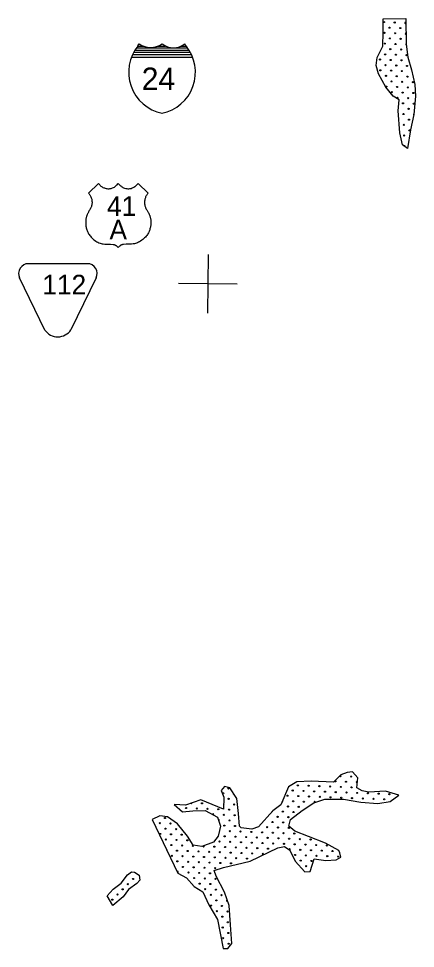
# Model space of a CAD drawing. Extents: x 1612280 to 1883141, y 560852 to 780851.
# Drawn here: x 1694945 to 1702393, y 716820 to 734263 of the extents above; entities that cross this region are included whole.
import ezdxf

# ---------------------------------------------------------------- set-up
doc = ezdxf.new("R2010")
doc.units = 0
for name, color, linetype in [('DESIGN - ROW - Easement Linework and Patterning', 7, 'Continuous'), ('DESIGN - SCRATCH - User 1', 7, 'Continuous'), ('DESIGN - TRAFFIC CONTROL PERMANENT - Pavement Marking Text', 7, 'Continuous'), ('SURVEY - DRAINAGE - Bridge Deck with Text', 7, 'Continuous'), ('SURVEY - DRAINAGE - Bridge Hydraulic Data - Points - Locators', 7, 'Continuous'), ('SURVEY - DRAINAGE - Bridge Hydraulic Data with Text', 7, 'Continuous')]:
    doc.layers.add(name, color=color, linetype=linetype)

msp = doc.modelspace()

# ---------------------------------------------------------------- linework, layer by layer
at = {"layer": 'DESIGN - ROW - Easement Linework and Patterning'}
for p, q in [((1696234, 729665), (1695130, 729665)), ((1696234, 729665), (1695130, 729665)), ((1695438, 728419), (1694963, 729399)), ((1695438, 728419), (1694963, 729399)), ((1696400, 729400), (1695927, 728422)), ((1696400, 729400), (1695927, 728422))]:
    msp.add_line(p, q, dxfattribs=at)
for centre, radius, start, end in [((1695130, 729480), 185, 90.0012, 205.8236), ((1695130, 729480), 185, 90.0012, 205.8236), ((1696234, 729480), 185, 334.1799, 90.0012), ((1696234, 729480), 185, 334.1799, 90.0012), ((1695681, 728591), 298, 215.137, 325.5451), ((1695681, 728591), 298, 215.137, 325.5451)]:
    msp.add_arc(centre, radius, start, end, dxfattribs=at)
at = {"layer": 'DESIGN - SCRATCH - User 1'}
for points in [[(1702243, 731826), (1702148, 731893), (1702103, 732117), (1702069, 732530), (1702086, 732737), (1701974, 732810), (1701840, 732977), (1701701, 733229), (1701656, 733385), (1701678, 733531), (1701779, 733743), (1701790, 734006), (1701790, 734257)], [(1702243, 731826), (1702148, 731893), (1702103, 732117), (1702069, 732530), (1702086, 732737), (1701974, 732810), (1701840, 732977), (1701701, 733229), (1701656, 733385), (1701678, 733531), (1701779, 733743), (1701790, 734006), (1701790, 734257)], [(1701790, 734257), (1702215, 734263)], [(1701790, 734257), (1702215, 734263)], [(1702215, 734263), (1702220, 733782), (1702254, 733542), (1702321, 733302), (1702382, 733028), (1702393, 732810), (1702365, 732463), (1702304, 732178), (1702243, 731826)], [(1702215, 734263), (1702220, 733782), (1702254, 733542), (1702321, 733302), (1702382, 733028), (1702393, 732810), (1702365, 732463), (1702304, 732178), (1702243, 731826)], [(1702085, 719696), (1701830, 719771), (1701520, 719751), (1701395, 719776), (1701295, 719831), (1701315, 720021), (1701210, 720131), (1701111, 720121), (1700996, 720076), (1700856, 719936), (1700436, 719956), (1700169, 719944)], [(1702085, 719696), (1701830, 719771), (1701520, 719751), (1701395, 719776), (1701295, 719831), (1701315, 720021), (1701210, 720131), (1701111, 720121), (1700996, 720076), (1700856, 719936), (1700436, 719956), (1700169, 719944)], [(1700169, 719944), (1700009, 719849), (1699869, 719514), (1699719, 719399), (1699450, 719099), (1699320, 719054), (1699120, 719079), (1699090, 719114), (1699070, 719349), (1699040, 719634), (1698910, 719829), (1698810, 719854), (1698745, 719779), (1698800, 719654), (1698790, 719429), (1698366, 719604), (1698076, 719509), (1697866, 719519)], [(1700169, 719944), (1700009, 719849), (1699869, 719514), (1699719, 719399), (1699450, 719099), (1699320, 719054), (1699120, 719079), (1699090, 719114), (1699070, 719349), (1699040, 719634), (1698910, 719829), (1698810, 719854), (1698745, 719779), (1698800, 719654), (1698790, 719429), (1698366, 719604), (1698076, 719509), (1697866, 719519)], [(1700494, 718499), (1700711, 718467), (1700906, 718482), (1700996, 718532), (1700976, 718612), (1700956, 718657), (1700706, 718792), (1700386, 718916), (1700127, 719021), (1700017, 719116), (1700047, 719236), (1700266, 719406), (1700486, 719551), (1700691, 719621), (1701041, 719621), (1701370, 719566), (1701690, 719541), (1701920, 719576), (1702085, 719696)], [(1700494, 718499), (1700711, 718467), (1700906, 718482), (1700996, 718532), (1700976, 718612), (1700956, 718657), (1700706, 718792), (1700386, 718916), (1700127, 719021), (1700017, 719116), (1700047, 719236), (1700266, 719406), (1700486, 719551), (1700691, 719621), (1701041, 719621), (1701370, 719566), (1701690, 719541), (1701920, 719576), (1702085, 719696)], [(1697866, 719519), (1698021, 719384), (1698216, 719399), (1698446, 719404), (1698676, 719284), (1698735, 719114), (1698691, 718924), (1698606, 718814), (1698386, 718734), (1698221, 718754), (1698116, 718924), (1697926, 719154), (1697737, 719289), (1697597, 719304), (1697452, 719239)], [(1697866, 719519), (1698021, 719384), (1698216, 719399), (1698446, 719404), (1698676, 719284), (1698735, 719114), (1698691, 718924), (1698606, 718814), (1698386, 718734), (1698221, 718754), (1698116, 718924), (1697926, 719154), (1697737, 719289), (1697597, 719304), (1697452, 719239)], [(1697452, 719239), (1697931, 718234)], [(1697452, 719239), (1697931, 718234)], [(1698616, 718279), (1698790, 718339), (1699290, 718454), (1699809, 718704), (1699939, 718729), (1700039, 718664), (1700139, 718459), (1700319, 718254), (1700419, 718264), (1700494, 718499)], [(1698616, 718279), (1698790, 718339), (1699290, 718454), (1699809, 718704), (1699939, 718729), (1700039, 718664), (1700139, 718459), (1700319, 718254), (1700419, 718264), (1700494, 718499)], [(1696605, 717803), (1696717, 717929), (1696871, 718043), (1696989, 718202), (1697067, 718258), (1697123, 718251), (1697205, 718191)], [(1696605, 717803), (1696717, 717929), (1696871, 718043), (1696989, 718202), (1697067, 718258), (1697123, 718251), (1697205, 718191)], [(1697205, 718191), (1697221, 718100), (1697163, 718040), (1697009, 717926), (1696905, 717786), (1696711, 717623)], [(1697205, 718191), (1697221, 718100), (1697163, 718040), (1697009, 717926), (1696905, 717786), (1696711, 717623)], [(1697931, 718234), (1698096, 718144), (1698241, 717984), (1698401, 717879), (1698516, 717639), (1698676, 717360), (1698785, 716820), (1698875, 716820), (1698945, 716910), (1698920, 717260), (1698895, 717624), (1698810, 717874), (1698656, 718174), (1698616, 718279)], [(1697931, 718234), (1698096, 718144), (1698241, 717984), (1698401, 717879), (1698516, 717639), (1698676, 717360), (1698785, 716820), (1698875, 716820), (1698945, 716910), (1698920, 717260), (1698895, 717624), (1698810, 717874), (1698656, 718174), (1698616, 718279)], [(1696711, 717623), (1696605, 717803)], [(1696711, 717623), (1696605, 717803)]]:
    msp.add_lwpolyline(points, dxfattribs=at)
for centre in [(1701952, 732883), (1701952, 732883), (1702057, 732778), (1702057, 732778), (1702161, 732674), (1702161, 732674), (1697820, 718557), (1697820, 718557), (1697925, 718452), (1697925, 718452)]:
    msp.add_circle(centre, 10.6, dxfattribs=at)
msp.add_arc((1697716, 718661), 10.6, 20.4261, 30.6046, dxfattribs=at)
at = {"layer": 'DESIGN - TRAFFIC CONTROL PERMANENT - Pavement Marking Text'}
for centre in [(1701803, 734197), (1701803, 734197), (1702004, 734189), (1702004, 734189), (1701810, 733995), (1701810, 733995), (1701907, 734092), (1701907, 734092), (1702109, 734085), (1702109, 734085), (1701915, 733891), (1701915, 733891), (1702012, 733988), (1702012, 733988), (1702116, 733883), (1702116, 733883), (1701818, 733794), (1701818, 733794), (1701922, 733689), (1701922, 733689), (1702019, 733786), (1702019, 733786), (1702124, 733682), (1702124, 733682), (1701728, 733495), (1701728, 733495), (1701825, 733592), (1701825, 733592), (1701930, 733487), (1701930, 733487), (1702027, 733585), (1702027, 733585), (1702131, 733480), (1702131, 733480), (1702229, 733577), (1702229, 733577), (1701736, 733293), (1701736, 733293), (1701833, 733390), (1701833, 733390), (1702034, 733383), (1702034, 733383), (1702236, 733375), (1702236, 733375), (1701840, 733189), (1701840, 733189), (1701937, 733286), (1701937, 733286), (1702042, 733181), (1702042, 733181), (1702139, 733278), (1702139, 733278), (1702243, 733174), (1702243, 733174), (1701848, 732987), (1701848, 732987), (1701945, 733084), (1701945, 733084), (1702049, 732980), (1702049, 732980), (1702146, 733077), (1702146, 733077), (1702251, 732972), (1702251, 732972), (1702348, 733069), (1702348, 733069), (1702154, 732875), (1702154, 732875), (1702258, 732771), (1702258, 732771), (1702355, 732868), (1702355, 732868), (1702363, 732666), (1702363, 732666), (1702169, 732472), (1702169, 732472), (1702266, 732569), (1702266, 732569), (1702176, 732270), (1702176, 732270), (1702273, 732367), (1702273, 732367), (1702281, 732166), (1702281, 732166), (1702184, 732069), (1702184, 732069), (1700986, 720050), (1700986, 720050), (1701188, 720043), (1701188, 720043), (1700187, 719878), (1700187, 719878), (1700389, 719871), (1700389, 719871), (1700591, 719864), (1700591, 719864), (1700889, 719953), (1700889, 719953), (1701091, 719946), (1701091, 719946), (1701293, 719938), (1701293, 719938), (1698784, 719729), (1698784, 719729), (1700090, 719781), (1700090, 719781), (1700292, 719774), (1700292, 719774), (1700494, 719766), (1700494, 719766), (1700695, 719759), (1700695, 719759), (1700792, 719856), (1700792, 719856), (1700897, 719751), (1700897, 719751), (1700994, 719849), (1700994, 719849), (1701098, 719744), (1701098, 719744), (1701195, 719841), (1701195, 719841), (1701300, 719737), (1701300, 719737), (1701502, 719729), (1701502, 719729), (1701703, 719722), (1701703, 719722), (1701905, 719714), (1701905, 719714), (1698388, 719542), (1698388, 719542), (1698888, 719625), (1698888, 719625), (1698993, 719520), (1698993, 719520), (1699993, 719684), (1699993, 719684), (1700098, 719580), (1700098, 719580), (1700195, 719677), (1700195, 719677), (1700299, 719572), (1700299, 719572), (1700396, 719669), (1700396, 719669), (1700598, 719662), (1700598, 719662), (1700800, 719654), (1700800, 719654), (1701001, 719647), (1701001, 719647), (1701203, 719639), (1701203, 719639), (1701405, 719632), (1701405, 719632), (1701606, 719625), (1701606, 719625), (1701808, 719617), (1701808, 719617), (1698089, 719453), (1698089, 719453), (1698291, 719445), (1698291, 719445), (1698492, 719438), (1698492, 719438), (1698694, 719430), (1698694, 719430), (1698896, 719423), (1698896, 719423), (1699904, 719386), (1699904, 719386), (1700001, 719483), (1700001, 719483), (1700105, 719378), (1700105, 719378), (1700202, 719475), (1700202, 719475), (1697596, 719169), (1697596, 719169), (1697693, 719266), (1697693, 719266), (1698799, 719326), (1698799, 719326), (1698903, 719221), (1698903, 719221), (1699000, 719318), (1699000, 719318), (1699710, 719191), (1699710, 719191), (1699807, 719289), (1699807, 719289), (1699911, 719184), (1699911, 719184), (1700008, 719281), (1700008, 719281), (1697701, 719065), (1697701, 719065), (1697798, 719162), (1697798, 719162), (1697902, 719057), (1697902, 719057), (1698806, 719124), (1698806, 719124), (1698911, 719020), (1698911, 719020), (1699008, 719117), (1699008, 719117), (1699112, 719012), (1699112, 719012), (1699314, 719005), (1699314, 719005), (1699515, 718997), (1699515, 718997), (1699612, 719094), (1699612, 719094), (1699717, 718990), (1699717, 718990), (1699814, 719087), (1699814, 719087), (1700016, 719079), (1700016, 719079), (1697604, 718967), (1697604, 718967), (1697708, 718863), (1697708, 718863), (1697805, 718960), (1697805, 718960), (1697910, 718855), (1697910, 718855), (1698007, 718953), (1698007, 718953), (1698112, 718848), (1698112, 718848), (1698716, 718826), (1698716, 718826), (1698813, 718923), (1698813, 718923), (1698918, 718818), (1698918, 718818), (1699015, 718915), (1699015, 718915), (1699217, 718908), (1699217, 718908), (1699418, 718900), (1699418, 718900), (1699620, 718893), (1699620, 718893), (1699822, 718885), (1699822, 718885), (1699919, 718982), (1699919, 718982), (1700023, 718878), (1700023, 718878), (1700120, 718975), (1700120, 718975), (1700225, 718870), (1700225, 718870), (1700426, 718863), (1700426, 718863), (1697813, 718758), (1697813, 718758), (1697917, 718654), (1697917, 718654), (1698014, 718751), (1698014, 718751), (1698119, 718646), (1698119, 718646), (1698216, 718743), (1698216, 718743), (1698619, 718729), (1698619, 718729), (1698821, 718721), (1698821, 718721), (1699023, 718714), (1699023, 718714), (1699120, 718811), (1699120, 718811), (1699224, 718706), (1699224, 718706), (1699321, 718803), (1699321, 718803), (1699426, 718699), (1699426, 718699), (1699523, 718796), (1699523, 718796), (1699627, 718691), (1699627, 718691), (1699724, 718788), (1699724, 718788), (1699926, 718781), (1699926, 718781), (1700128, 718773), (1700128, 718773), (1700232, 718669), (1700232, 718669), (1700329, 718766), (1700329, 718766), (1700434, 718661), (1700434, 718661), (1700531, 718758), (1700531, 718758), (1700635, 718654), (1700635, 718654), (1700732, 718751), (1700732, 718751), (1700837, 718646), (1700837, 718646), (1698022, 718549), (1698022, 718549), (1698224, 718542), (1698224, 718542), (1698321, 718639), (1698321, 718639), (1698425, 718534), (1698425, 718534), (1698522, 718631), (1698522, 718631), (1698627, 718527), (1698627, 718527), (1698724, 718624), (1698724, 718624), (1698828, 718519), (1698828, 718519), (1698925, 718617), (1698925, 718617), (1699030, 718512), (1699030, 718512), (1699127, 718609), (1699127, 718609), (1699232, 718505), (1699232, 718505), (1699329, 718602), (1699329, 718602), (1699530, 718594), (1699530, 718594), (1700135, 718572), (1700135, 718572), (1700240, 718467), (1700240, 718467), (1700337, 718564), (1700337, 718564), (1700538, 718557), (1700538, 718557), (1700740, 718549), (1700740, 718549), (1700942, 718542), (1700942, 718542), (1698029, 718348), (1698029, 718348), (1698126, 718445), (1698126, 718445), (1698231, 718340), (1698231, 718340), (1698328, 718437), (1698328, 718437), (1698433, 718333), (1698433, 718333), (1698530, 718430), (1698530, 718430), (1698634, 718325), (1698634, 718325), (1698731, 718422), (1698731, 718422), (1698933, 718415), (1698933, 718415), (1700344, 718363), (1700344, 718363), (1700441, 718460), (1700441, 718460), (1697094, 718122), (1697094, 718122), (1698134, 718243), (1698134, 718243), (1698239, 718139), (1698239, 718139), (1698336, 718236), (1698336, 718236), (1698440, 718131), (1698440, 718131), (1698537, 718228), (1698537, 718228), (1698642, 718124), (1698642, 718124), (1696997, 718025), (1696997, 718025), (1698343, 718034), (1698343, 718034), (1698545, 718027), (1698545, 718027), (1696802, 717831), (1696802, 717831), (1696899, 717928), (1696899, 717928), (1698448, 717930), (1698448, 717930), (1698552, 717825), (1698552, 717825), (1698649, 717922), (1698649, 717922), (1698754, 717818), (1698754, 717818), (1696705, 717734), (1696705, 717734), (1698560, 717623), (1698560, 717623), (1698657, 717720), (1698657, 717720), (1698761, 717616), (1698761, 717616), (1698664, 717519), (1698664, 717519), (1698866, 717511), (1698866, 717511), (1698769, 717414), (1698769, 717414), (1698873, 717310), (1698873, 717310), (1698776, 717213), (1698776, 717213), (1698881, 717108), (1698881, 717108), (1698784, 717011), (1698784, 717011), (1698888, 716907), (1698888, 716907)]:
    msp.add_circle(centre, 10.6, dxfattribs=at)
for centre, start, end in [((1702206, 734182), 27.3445, 333.9866), ((1702214, 733980), 66.5709, 294.7602), ((1702221, 733779), 95.0843, 275.9552), ((1702064, 732576), 322.5526, 28.1804), ((1702370, 732464), 112.9176, 231.8269), ((1702072, 732375), 351.0207, 18.2437), ((1702191, 731867), 303.8118, 165.7174), ((1698881, 719826), 101.2616, 50.6468), ((1698985, 719722), 140.2991, 287.0471), ((1698186, 719550), 225.434, 350.8632), ((1698791, 719527), 288.2692, 66.6438), ((1699896, 719587), 266.9188, 47.7462), ((1700501, 719565), 328.8894, 248.8359), ((1699702, 719393), 288.2506, 347.8121), ((1698597, 719333), 286.9978, 197.8665), ((1698701, 719229), 253.8989, 144.9583), ((1698709, 719027), 290.5645, 42.8003), ((1698418, 718736), 141.0263, 78.9626), ((1700031, 718676), 295.1409, 178.7725), ((1697932, 718251), 246.2521, 164.7786), ((1698746, 718019), 180.5046, 234.1114), ((1698858, 717713), 70.0601, 327.4748), ((1698791, 716809), 76.5509, 103.4491)]:
    msp.add_arc(centre, 10.6, start, end, dxfattribs=at)
at = {"layer": 'SURVEY - DRAINAGE - Bridge Deck with Text'}
for points in [[(1696258, 730986), (1696445, 731172), (1696455, 731159), (1696467, 731144), (1696479, 731132), (1696490, 731122), (1696503, 731113), (1696516, 731104), (1696528, 731097), (1696542, 731090), (1696556, 731085), (1696572, 731080), (1696588, 731076), (1696604, 731074), (1696622, 731072), (1696630, 731072), (1696638, 731072), (1696646, 731072), (1696656, 731073), (1696666, 731075), (1696680, 731077), (1696692, 731081), (1696710, 731087), (1696728, 731094), (1696744, 731103), (1696758, 731112), (1696772, 731123), (1696785, 731135), (1696797, 731147), (1696808, 731161), (1696816, 731172), (1696823, 731163), (1696832, 731151), (1696840, 731142), (1696849, 731133), (1696861, 731123), (1696873, 731113), (1696886, 731104), (1696900, 731097), (1696916, 731089), (1696935, 731082), (1696956, 731077), (1696977, 731073), (1696995, 731072), (1697015, 731072), (1697035, 731074), (1697055, 731078), (1697077, 731085), (1697095, 731093), (1697110, 731100), (1697127, 731110), (1697141, 731121), (1697157, 731135), (1697167, 731146), (1697177, 731158), (1697187, 731172), (1697374, 730986)], [(1696258, 730986), (1696445, 731172), (1696455, 731159), (1696467, 731144), (1696479, 731132), (1696490, 731122), (1696503, 731113), (1696516, 731104), (1696528, 731097), (1696542, 731090), (1696556, 731085), (1696572, 731080), (1696588, 731076), (1696604, 731074), (1696622, 731072), (1696630, 731072), (1696638, 731072), (1696646, 731072), (1696656, 731073), (1696666, 731075), (1696680, 731077), (1696692, 731081), (1696710, 731087), (1696728, 731094), (1696744, 731103), (1696758, 731112), (1696772, 731123), (1696785, 731135), (1696797, 731147), (1696808, 731161), (1696816, 731172), (1696823, 731163), (1696832, 731151), (1696840, 731142), (1696849, 731133), (1696861, 731123), (1696873, 731113), (1696886, 731104), (1696900, 731097), (1696916, 731089), (1696935, 731082), (1696956, 731077), (1696977, 731073), (1696995, 731072), (1697015, 731072), (1697035, 731074), (1697055, 731078), (1697077, 731085), (1697095, 731093), (1697110, 731100), (1697127, 731110), (1697141, 731121), (1697157, 731135), (1697167, 731146), (1697177, 731158), (1697187, 731172), (1697374, 730986)], [(1696258, 730986), (1696267, 730975), (1696275, 730965), (1696282, 730954), (1696289, 730943), (1696296, 730931), (1696302, 730917), (1696308, 730903), (1696313, 730887), (1696317, 730873), (1696320, 730857), (1696322, 730839), (1696323, 730818), (1696323, 730801), (1696321, 730785), (1696319, 730771), (1696316, 730753), (1696312, 730739), (1696307, 730726), (1696302, 730714), (1696297, 730704), (1696290, 730690), (1696282, 730677), (1696272, 730660), (1696259, 730639), (1696255, 730633), (1696249, 730622), (1696243, 730608), (1696239, 730599), (1696234, 730588), (1696230, 730578), (1696226, 730567), (1696222, 730555), (1696218, 730542), (1696215, 730529), (1696212, 730518), (1696210, 730506), (1696208, 730494), (1696206, 730481), (1696205, 730469), (1696204, 730458), (1696204, 730447), (1696204, 730436), (1696204, 730423), (1696204, 730412), (1696205, 730397), (1696207, 730382), (1696209, 730367), (1696212, 730352), (1696216, 730336), (1696221, 730317), (1696226, 730302), (1696232, 730285), (1696238, 730271), (1696243, 730259), (1696250, 730245), (1696260, 730227), (1696269, 730213), (1696281, 730195), (1696294, 730179), (1696308, 730162), (1696322, 730147), (1696334, 730135), (1696351, 730120), (1696371, 730105), (1696395, 730089), (1696416, 730077), (1696435, 730067), (1696453, 730059), (1696474, 730051), (1696493, 730045), (1696513, 730039), (1696522, 730037), (1696535, 730035), (1696565, 730033), (1696671, 730029), (1696718, 730027), (1696723, 730026), (1696728, 730025), (1696733, 730024), (1696738, 730022), (1696743, 730021), (1696747, 730019), (1696753, 730017), (1696757, 730015), (1696762, 730013), (1696766, 730011), (1696770, 730008), (1696779, 730003), (1696788, 729996), (1696796, 729989), (1696804, 729981), (1696810, 729974), (1696816, 729966)], [(1696258, 730986), (1696267, 730975), (1696275, 730965), (1696282, 730954), (1696289, 730943), (1696296, 730931), (1696302, 730917), (1696308, 730903), (1696313, 730887), (1696317, 730873), (1696320, 730857), (1696322, 730839), (1696323, 730818), (1696323, 730801), (1696321, 730785), (1696319, 730771), (1696316, 730753), (1696312, 730739), (1696307, 730726), (1696302, 730714), (1696297, 730704), (1696290, 730690), (1696282, 730677), (1696272, 730660), (1696259, 730639), (1696255, 730633), (1696249, 730622), (1696243, 730608), (1696239, 730599), (1696234, 730588), (1696230, 730578), (1696226, 730567), (1696222, 730555), (1696218, 730542), (1696215, 730529), (1696212, 730518), (1696210, 730506), (1696208, 730494), (1696206, 730481), (1696205, 730469), (1696204, 730458), (1696204, 730447), (1696204, 730436), (1696204, 730423), (1696204, 730412), (1696205, 730397), (1696207, 730382), (1696209, 730367), (1696212, 730352), (1696216, 730336), (1696221, 730317), (1696226, 730302), (1696232, 730285), (1696238, 730271), (1696243, 730259), (1696250, 730245), (1696260, 730227), (1696269, 730213), (1696281, 730195), (1696294, 730179), (1696308, 730162), (1696322, 730147), (1696334, 730135), (1696351, 730120), (1696371, 730105), (1696395, 730089), (1696416, 730077), (1696435, 730067), (1696453, 730059), (1696474, 730051), (1696493, 730045), (1696513, 730039), (1696522, 730037), (1696535, 730035), (1696565, 730033), (1696671, 730029), (1696718, 730027), (1696723, 730026), (1696728, 730025), (1696733, 730024), (1696738, 730022), (1696743, 730021), (1696747, 730019), (1696753, 730017), (1696757, 730015), (1696762, 730013), (1696766, 730011), (1696770, 730008), (1696779, 730003), (1696788, 729996), (1696796, 729989), (1696804, 729981), (1696810, 729974), (1696816, 729966)], [(1697374, 730986), (1697365, 730975), (1697357, 730965), (1697349, 730954), (1697343, 730943), (1697336, 730931), (1697330, 730917), (1697324, 730903), (1697319, 730887), (1697315, 730873), (1697312, 730857), (1697310, 730839), (1697308, 730818), (1697309, 730801), (1697310, 730785), (1697312, 730771), (1697316, 730753), (1697320, 730739), (1697325, 730726), (1697330, 730714), (1697334, 730704), (1697342, 730690), (1697349, 730677), (1697360, 730660), (1697373, 730639), (1697376, 730633), (1697382, 730622), (1697389, 730608), (1697393, 730599), (1697398, 730588), (1697402, 730578), (1697406, 730567), (1697410, 730555), (1697413, 730542), (1697417, 730529), (1697419, 730518), (1697422, 730506), (1697424, 730494), (1697425, 730481), (1697427, 730469), (1697427, 730458), (1697428, 730447), (1697428, 730436), (1697428, 730423), (1697427, 730412), (1697426, 730397), (1697425, 730382), (1697423, 730367), (1697420, 730352), (1697416, 730336), (1697411, 730317), (1697406, 730302), (1697400, 730285), (1697394, 730271), (1697389, 730259), (1697381, 730245), (1697372, 730227), (1697362, 730213), (1697350, 730195), (1697338, 730179), (1697324, 730162), (1697310, 730147), (1697297, 730135), (1697280, 730120), (1697261, 730105), (1697236, 730089), (1697216, 730077), (1697197, 730067), (1697179, 730059), (1697158, 730051), (1697139, 730045), (1697119, 730039), (1697109, 730037), (1697097, 730035), (1697067, 730033), (1696961, 730029), (1696913, 730027), (1696909, 730026), (1696904, 730025), (1696899, 730024), (1696894, 730022), (1696889, 730021), (1696884, 730019), (1696879, 730017), (1696875, 730015), (1696870, 730013), (1696866, 730011), (1696862, 730008), (1696853, 730003), (1696844, 729996), (1696835, 729989), (1696828, 729981), (1696821, 729974), (1696816, 729966)], [(1697374, 730986), (1697365, 730975), (1697357, 730965), (1697349, 730954), (1697343, 730943), (1697336, 730931), (1697330, 730917), (1697324, 730903), (1697319, 730887), (1697315, 730873), (1697312, 730857), (1697310, 730839), (1697308, 730818), (1697309, 730801), (1697310, 730785), (1697312, 730771), (1697316, 730753), (1697320, 730739), (1697325, 730726), (1697330, 730714), (1697334, 730704), (1697342, 730690), (1697349, 730677), (1697360, 730660), (1697373, 730639), (1697376, 730633), (1697382, 730622), (1697389, 730608), (1697393, 730599), (1697398, 730588), (1697402, 730578), (1697406, 730567), (1697410, 730555), (1697413, 730542), (1697417, 730529), (1697419, 730518), (1697422, 730506), (1697424, 730494), (1697425, 730481), (1697427, 730469), (1697427, 730458), (1697428, 730447), (1697428, 730436), (1697428, 730423), (1697427, 730412), (1697426, 730397), (1697425, 730382), (1697423, 730367), (1697420, 730352), (1697416, 730336), (1697411, 730317), (1697406, 730302), (1697400, 730285), (1697394, 730271), (1697389, 730259), (1697381, 730245), (1697372, 730227), (1697362, 730213), (1697350, 730195), (1697338, 730179), (1697324, 730162), (1697310, 730147), (1697297, 730135), (1697280, 730120), (1697261, 730105), (1697236, 730089), (1697216, 730077), (1697197, 730067), (1697179, 730059), (1697158, 730051), (1697139, 730045), (1697119, 730039), (1697109, 730037), (1697097, 730035), (1697067, 730033), (1696961, 730029), (1696913, 730027), (1696909, 730026), (1696904, 730025), (1696899, 730024), (1696894, 730022), (1696889, 730021), (1696884, 730019), (1696879, 730017), (1696875, 730015), (1696870, 730013), (1696866, 730011), (1696862, 730008), (1696853, 730003), (1696844, 729996), (1696835, 729989), (1696828, 729981), (1696821, 729974), (1696816, 729966)]]:
    msp.add_lwpolyline(points, dxfattribs=at)
at = {"layer": 'SURVEY - DRAINAGE - Bridge Hydraulic Data - Points - Locators'}
for p, q in [((1698501, 729838), (1698490, 728738)), ((1698501, 729838), (1698490, 728738)), ((1699046, 729283), (1697946, 729293)), ((1699046, 729283), (1697946, 729293))]:
    msp.add_line(p, q, dxfattribs=at)
at = {"layer": 'SURVEY - DRAINAGE - Bridge Hydraulic Data with Text'}
for p, q in [((1697133, 733669), (1698139, 733669)), ((1697133, 733669), (1698139, 733669)), ((1697157, 733714), (1698114, 733714)), ((1697157, 733714), (1698114, 733714)), ((1697182, 733746), (1697289, 733746)), ((1697182, 733746), (1697289, 733746)), ((1697558, 733746), (1697705, 733746)), ((1697558, 733746), (1697705, 733746)), ((1697991, 733746), (1698091, 733746)), ((1697991, 733746), (1698091, 733746)), ((1697066, 733539), (1698203, 733539)), ((1697066, 733539), (1698203, 733539)), ((1697086, 733590), (1698183, 733590)), ((1697086, 733590), (1698183, 733590)), ((1697107, 733630), (1698163, 733630)), ((1697107, 733630), (1698163, 733630))]:
    msp.add_line(p, q, dxfattribs=at)
for points in [[(1697186, 733753), (1697209, 733792)], [(1697186, 733753), (1697209, 733792)], [(1698087, 733750), (1698067, 733790)], [(1698087, 733750), (1698067, 733790)]]:
    msp.add_lwpolyline(points, dxfattribs=at)
for centre, radius, start, end in [((1697798, 733258), 787, 140.9901, 258.178), ((1697798, 733258), 787, 140.9901, 258.178), ((1697425, 734091), 370, 234.1647, 305.144), ((1697425, 734091), 370, 234.1647, 305.144), ((1697482, 733254), 782, 281.2226, 39.2925), ((1697482, 733254), 782, 281.2226, 39.2925), ((1697852, 734066), 350, 232.3625, 307.9876), ((1697852, 734066), 350, 232.3625, 307.9876)]:
    msp.add_arc(centre, radius, start, end, dxfattribs=at)

# ---------------------------------------------------------------- texts
at = {"layer": 'DESIGN - ROW - Easement Linework and Patterning'}
msp.add_text('112', height=369.6, rotation=0.0012, dxfattribs=at).set_placement((1695389, 729087))
msp.add_text('112', height=369.6, rotation=0.0012, dxfattribs=at).set_placement((1695389, 729087))
at = {"layer": 'SURVEY - DRAINAGE - Bridge Deck with Text'}
for s, height, p in [('41', 369.6, (1696604, 730560)), ('41', 369.6, (1696604, 730560)), ('A', 370, (1696650, 730119)), ('A', 370, (1696650, 730119))]:
    msp.add_text(s, height=height, rotation=0.0014, dxfattribs=at).set_placement(p)
at = {"layer": 'SURVEY - DRAINAGE - Bridge Hydraulic Data with Text'}
msp.add_text('24', height=422.4, rotation=0.0013, dxfattribs=at).set_placement((1697256, 732922))
msp.add_text('24', height=422.4, rotation=0.0013, dxfattribs=at).set_placement((1697256, 732922))

doc.saveas('drawing.dxf')
